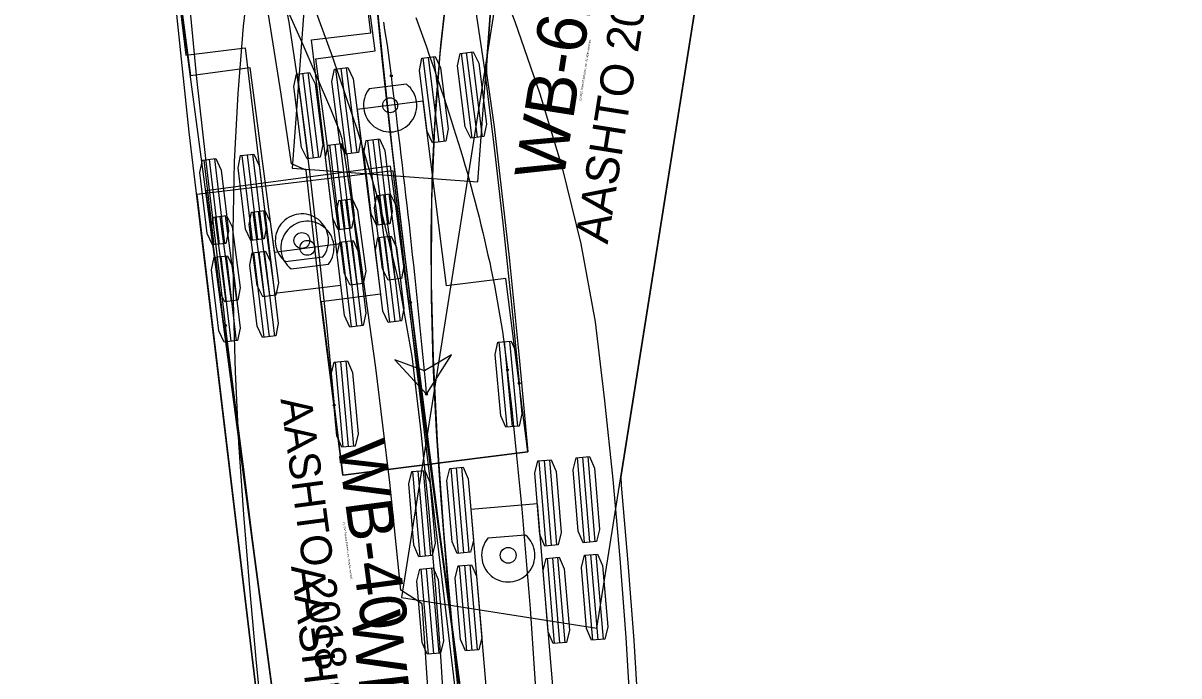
# Model space of a CAD drawing. Extents: x 1600240 to 1604759, y 285789 to 289704.
# Drawn here: x 1601615.79 to 1601665.41, y 286611.22 to 286639.24 of the extents above; entities that cross this region are included whole.
import ezdxf

# ---------------------------------------------------------------- set-up
doc = ezdxf.new("R2010")
doc.units = 0
for name, color, linetype in [('MT_P_CL_Double_Solid', 7, 'Continuous'), ('MT_X_Edge_Line', 7, 'Continuous'), ('TR_Turning_Path2', 7, 'Continuous'), ('TR_Turning_Path3', 7, 'Continuous'), ('TR_Turning_Path4', 7, 'Continuous')]:
    doc.layers.add(name, color=color, linetype=linetype)

msp = doc.modelspace()

# ---------------------------------------------------------------- linework, layer by layer
at = {"layer": 'MT_P_CL_Double_Solid'}
for p, q in [((1601630.904, 286638.054), (1601629.914, 286645.489)), ((1601621.984, 286644.432), (1601622.974, 286636.997)), ((1601628.36, 286637.715), (1601630.904, 286638.054)), ((1601622.974, 286636.997), (1601625.519, 286637.336)), ((1601625.519, 286637.336), (1601626.575, 286629.407)), ((1601629.417, 286629.785), (1601628.36, 286637.715)), ((1601631.565, 286633.098), (1601623.635, 286632.041)), ((1601635.924, 286600.387), (1601631.565, 286633.098)), ((1601623.635, 286632.041), (1601627.995, 286599.33)), ((1601623.635, 286632.041), (1601623.635, 286632.041)), ((1601631.038, 286631.851), (1601631.522, 286628.216)), ((1601631.265, 286631.881), (1601631.749, 286628.247)), ((1601631.492, 286631.911), (1601631.976, 286628.277)), ((1601629.402, 286631.633), (1601629.886, 286627.998)), ((1601629.629, 286631.663), (1601630.114, 286628.029)), ((1601629.856, 286631.693), (1601630.341, 286628.059)), ((1601624.016, 286630.915), (1601624.501, 286627.281)), ((1601624.243, 286630.945), (1601624.728, 286627.311)), ((1601624.471, 286630.976), (1601624.955, 286627.341)), ((1601625.652, 286631.133), (1601626.136, 286627.499)), ((1601625.879, 286631.163), (1601626.363, 286627.529)), ((1601626.106, 286631.194), (1601626.591, 286627.559)), ((1601626.575, 286629.407), (1601629.417, 286629.785)), ((1601627.302, 286628.688), (1601628.904, 286628.902))]:
    msp.add_line(p, q, dxfattribs=at)
for points in [[(1601624.486, 286626.267), (1601624.405, 286626.931), (1601624.004, 286630.248), (1601623.618, 286633.563), (1601623.255, 286636.871), (1601622.929, 286640.166), (1601622.653, 286643.44), (1601622.445, 286646.681), (1601622.323, 286649.878), (1601622.303, 286653.051), (1601622.401, 286656.2), (1601622.632, 286659.317), (1601623.004, 286662.393), (1601623.528, 286665.418), (1601624.209, 286668.384), (1601625.051, 286671.279), (1601626.056, 286674.095), (1601627.225, 286676.82), (1601628.556, 286679.444), (1601629.583, 286681.214)], [(1601632.426, 286627.244), (1601632.345, 286627.903), (1601631.948, 286631.194), (1601631.567, 286634.468), (1601631.211, 286637.711), (1601630.894, 286640.909), (1601630.63, 286644.047), (1601630.434, 286647.107), (1601630.321, 286650.076), (1601630.303, 286652.973), (1601630.392, 286655.803), (1601630.596, 286658.564), (1601630.923, 286661.252), (1601631.376, 286663.864), (1601631.958, 286666.395), (1601632.67, 286668.841), (1601633.512, 286671.196), (1601634.483, 286673.455), (1601635.579, 286675.612), (1601636.419, 286677.058)], [(1601633.596, 286671.411), (1601633.041, 286669.939), (1601632.543, 286668.446), (1601632.019, 286666.63), (1601631.64, 286665.099), (1601631.254, 286663.244), (1601630.894, 286661.06), (1601630.624, 286658.856), (1601630.44, 286656.637), (1601630.333, 286654.405), (1601630.297, 286652.164), (1601630.333, 286649.594), (1601630.438, 286647.019), (1601630.624, 286644.118), (1601630.866, 286641.217), (1601631.215, 286637.672), (1601631.642, 286633.807), (1601632.214, 286628.979), (1601633.671, 286617.403), (1601635.924, 286600.387), (1601627.995, 286599.33), (1601627.804, 286600.759)], [(1601627.804, 286600.759), (1601621.95, 286644.686), (1601621.785, 286646.064), (1601621.198, 286651.595), (1601620.682, 286656.836), (1601620.199, 286662.153), (1601619.748, 286667.57), (1601619.644, 286669.39), (1601619.607, 286670.84)], [(1601635.33, 286604.848), (1601634.89, 286608.147), (1601634.453, 286611.443), (1601634.019, 286614.736), (1601633.59, 286618.029), (1601633.168, 286621.32), (1601632.752, 286624.611), (1601632.426, 286627.244)], [(1601627.4, 286603.791), (1601626.96, 286607.092), (1601626.522, 286610.393), (1601626.087, 286613.696), (1601625.657, 286617.001), (1601625.232, 286620.309), (1601624.814, 286623.618), (1601624.486, 286626.267)]]:
    msp.add_lwpolyline(points, dxfattribs=at)
for points in [[(1601630.981, 286631.843), (1601631.548, 286631.919), (1601631.787, 286631.433), (1601632.136, 286628.816), (1601632.033, 286628.284), (1601631.466, 286628.209), (1601631.227, 286628.695), (1601630.878, 286631.312)], [(1601629.346, 286631.625), (1601629.913, 286631.701), (1601630.151, 286631.215), (1601630.5, 286628.598), (1601630.397, 286628.066), (1601629.83, 286627.991), (1601629.591, 286628.477), (1601629.243, 286631.094)], [(1601623.96, 286630.908), (1601624.527, 286630.983), (1601624.766, 286630.497), (1601625.114, 286627.88), (1601625.011, 286627.349), (1601624.444, 286627.273), (1601624.206, 286627.759), (1601623.857, 286630.376)], [(1601625.595, 286631.126), (1601626.162, 286631.201), (1601626.401, 286630.715), (1601626.75, 286628.098), (1601626.647, 286627.567), (1601626.08, 286627.491), (1601625.841, 286627.977), (1601625.492, 286630.594)]]:
    msp.add_lwpolyline(points, close=True, dxfattribs=at)
for centre, radius in [((1601627.996, 286629.596), 0.32), ((1601632.426, 286627.244), 0.0417), ((1601632.426, 286627.244), 0.0417), ((1601624.486, 286626.267), 0.0417), ((1601624.486, 286626.267), 0.0417)]:
    msp.add_circle(centre, radius, dxfattribs=at)
msp.add_arc((1601627.996, 286629.596), 1.143, 322.5914, 232.5914, dxfattribs=at)
at = {"layer": 'MT_X_Edge_Line'}
msp.add_arc((1602837.866, 287782.942), 1921, 229.7619, 229.7619, dxfattribs=at)
at = {"layer": 'TR_Turning_Path2'}
for p, q in [((1601629.768, 286665.929), (1601627.338, 286633.019)), ((1601635.316, 286632.43), (1601637.747, 286665.34)), ((1601633.882, 286634.163), (1601633.423, 286637.801)), ((1601635.064, 286634.312), (1601634.605, 286637.95)), ((1601635.292, 286634.341), (1601634.832, 286637.979)), ((1601635.519, 286634.369), (1601635.06, 286638.007)), ((1601629.901, 286633.66), (1601629.442, 286637.298)), ((1601630.128, 286633.689), (1601629.669, 286637.327)), ((1601633.427, 286634.105), (1601632.968, 286637.743)), ((1601633.655, 286634.134), (1601633.195, 286637.772)), ((1601628.037, 286633.425), (1601627.577, 286637.063)), ((1601628.264, 286633.454), (1601627.805, 286637.091)), ((1601628.491, 286633.482), (1601628.032, 286637.12)), ((1601629.674, 286633.632), (1601629.214, 286637.269)), ((1601632.249, 286636.619), (1601630.645, 286636.417)), ((1601632.97, 286635.896), (1601630.126, 286635.537)), ((1601633.972, 286627.959), (1601632.97, 286635.896)), ((1601630.126, 286635.537), (1601631.128, 286627.6)), ((1601627.338, 286633.019), (1601635.316, 286632.43)), ((1601635.316, 286632.43), (1601635.316, 286632.43)), ((1601636.519, 286628.28), (1601633.972, 286627.959)), ((1601637.458, 286620.839), (1601636.519, 286628.28)), ((1601631.128, 286627.6), (1601628.582, 286627.278)), ((1601628.582, 286627.278), (1601629.521, 286619.837)), ((1601636.57, 286621.896), (1601636.232, 286625.547)), ((1601636.798, 286621.917), (1601636.461, 286625.568)), ((1601637.026, 286621.938), (1601636.689, 286625.589)), ((1601629.538, 286621.04), (1601629.203, 286624.691)), ((1601629.766, 286621.061), (1601629.431, 286624.712)), ((1601629.994, 286621.082), (1601629.659, 286624.733)), ((1601629.521, 286619.837), (1601637.458, 286620.839)), ((1601637.458, 286620.839), (1601637.458, 286620.839))]:
    msp.add_line(p, q, dxfattribs=at)
for points in [[(1601621.785, 286664.025), (1601621.952, 286662.949), (1601622.604, 286659.411), (1601623.361, 286655.937), (1601624.18, 286652.522), (1601625.016, 286649.158), (1601625.826, 286645.835), (1601626.568, 286642.545), (1601627.202, 286639.282), (1601627.69, 286636.036), (1601628.097, 286632.743), (1601628.475, 286629.447), (1601628.824, 286626.147), (1601629.142, 286622.845)], [(1601629.677, 286663.347), (1601629.863, 286662.452), (1601630.549, 286659.447), (1601631.309, 286656.419), (1601632.111, 286653.36), (1601632.926, 286650.258), (1601633.718, 286647.104), (1601634.452, 286643.89), (1601635.091, 286640.609), (1601635.595, 286637.259), (1601636.013, 286633.896), (1601636.401, 286630.529), (1601636.759, 286627.159), (1601637.086, 286623.785)], [(1601637.473, 286661.627), (1601635.686, 286637.432), (1601635.678, 286637.097), (1601636.014, 286634.793), (1601636.658, 286629.187), (1601637.093, 286624.893), (1601637.458, 286620.839), (1601629.521, 286619.837), (1601628.579, 286627.299), (1601627.949, 286632.938), (1601627.311, 286633.207), (1601626.873, 286636.188), (1601626.022, 286641.522)], [(1601631.258, 286639.288), (1601631.312, 286638.959), (1601631.364, 286638.63), (1601631.414, 286638.3), (1601631.463, 286637.971), (1601631.51, 286637.641), (1601631.556, 286637.31), (1601631.599, 286636.98)], [(1601633.114, 286623.315), (1601634.181, 286625.006), (1601633.022, 286624.31), (1601631.756, 286624.783), (1601633.114, 286623.315)]]:
    msp.add_lwpolyline(points, dxfattribs=at)
for points in [[(1601633.938, 286634.17), (1601633.371, 286634.098), (1601633.136, 286634.586), (1601632.805, 286637.205), (1601632.912, 286637.736), (1601633.479, 286637.808), (1601633.714, 286637.32), (1601634.045, 286634.701)], [(1601635.575, 286634.377), (1601635.008, 286634.305), (1601634.773, 286634.793), (1601634.442, 286637.412), (1601634.549, 286637.943), (1601635.116, 286638.014), (1601635.351, 286637.527), (1601635.682, 286634.907)], [(1601630.185, 286633.696), (1601629.617, 286633.624), (1601629.382, 286634.112), (1601629.051, 286636.731), (1601629.158, 286637.262), (1601629.726, 286637.334), (1601629.961, 286636.846), (1601630.291, 286634.227)], [(1601628.548, 286633.489), (1601627.98, 286633.418), (1601627.745, 286633.905), (1601627.414, 286636.525), (1601627.521, 286637.056), (1601628.089, 286637.127), (1601628.324, 286636.64), (1601628.654, 286634.02)], [(1601637.083, 286621.944), (1601636.513, 286621.891), (1601636.294, 286622.386), (1601636.051, 286625.015), (1601636.176, 286625.542), (1601636.745, 286625.595), (1601636.964, 286625.099), (1601637.207, 286622.471)], [(1601633.114, 286623.315), (1601634.181, 286625.006), (1601633.022, 286624.31), (1601631.756, 286624.783)], [(1601630.051, 286621.087), (1601629.481, 286621.035), (1601629.263, 286621.53), (1601629.021, 286624.159), (1601629.146, 286624.686), (1601629.716, 286624.738), (1601629.934, 286624.243), (1601630.175, 286621.614)]]:
    msp.add_lwpolyline(points, close=True, dxfattribs=at)
for centre, radius in [((1601631.599, 286636.98), 0.0417), ((1601631.599, 286636.98), 0.0417), ((1601631.548, 286635.716), 0.32), ((1601637.086, 286623.785), 0.0417), ((1601633.114, 286623.315), 0.0417), ((1601629.142, 286622.845), 0.0417)]:
    msp.add_circle(centre, radius, dxfattribs=at)
for centre, radius, start, end in [((1601264.185, 286589.342), 370.49, 5.26113, 7.38754), ((1601631.548, 286635.716), 1.143, 142.195, 52.195)]:
    msp.add_arc(centre, radius, start, end, dxfattribs=at)
at = {"layer": 'TR_Turning_Path3'}
for p, q in [((1601630.72, 286638.826), (1601628.933, 286653.719)), ((1601620.99, 286652.766), (1601622.777, 286637.873)), ((1601628.171, 286638.52), (1601630.72, 286638.826)), ((1601629.434, 286627.996), (1601628.171, 286638.52)), ((1601622.777, 286637.873), (1601625.325, 286638.179)), ((1601625.325, 286638.179), (1601626.587, 286627.654)), ((1601628.943, 286634.013), (1601629.379, 286630.373)), ((1601629.17, 286634.041), (1601629.607, 286630.4)), ((1601629.398, 286634.068), (1601629.834, 286630.427)), ((1601630.581, 286634.21), (1601631.018, 286630.569)), ((1601630.808, 286634.237), (1601631.245, 286630.597)), ((1601631.036, 286634.264), (1601631.473, 286630.624)), ((1601623.548, 286633.366), (1601623.985, 286629.726)), ((1601623.776, 286633.394), (1601624.212, 286629.753)), ((1601624.003, 286633.421), (1601624.44, 286629.78)), ((1601625.186, 286633.563), (1601625.623, 286629.922)), ((1601625.414, 286633.59), (1601625.85, 286629.949)), ((1601625.641, 286633.617), (1601626.078, 286629.977)), ((1601631.682, 286632.898), (1601623.243, 286631.886)), ((1601637.399, 286585.24), (1601631.682, 286632.898)), ((1601623.243, 286631.886), (1601628.959, 286584.228)), ((1601623.243, 286631.886), (1601623.243, 286631.886)), ((1601629.443, 286629.843), (1601629.88, 286626.203)), ((1601629.67, 286629.871), (1601630.107, 286626.23)), ((1601629.898, 286629.898), (1601630.335, 286626.257)), ((1601631.081, 286630.04), (1601631.518, 286626.399)), ((1601631.309, 286630.067), (1601631.745, 286626.426)), ((1601631.536, 286630.094), (1601631.973, 286626.454)), ((1601625.686, 286629.393), (1601626.123, 286625.752)), ((1601625.914, 286629.42), (1601626.351, 286625.779)), ((1601626.142, 286629.447), (1601626.578, 286625.807)), ((1601624.048, 286629.196), (1601624.485, 286625.556)), ((1601624.276, 286629.223), (1601624.712, 286625.583)), ((1601624.503, 286629.251), (1601624.94, 286625.61)), ((1601627.054, 286629.011), (1601628.659, 286629.204)), ((1601626.587, 286627.654), (1601629.434, 286627.996))]:
    msp.add_line(p, q, dxfattribs=at)
for points in [[(1601628.788, 286585.657), (1601622.925, 286634.563), (1601622.405, 286639.474), (1601621.992, 286644.416), (1601620.944, 286653.156), (1601620.831, 286654.263), (1601620.727, 286655.731), (1601620.676, 286657.19), (1601620.707, 286661.917), (1601620.793, 286665.212), (1601620.912, 286668.155), (1601621, 286669.627), (1601621.142, 286671.084)], [(1601626.64, 286603.897), (1601626.494, 286605.221), (1601626.143, 286608.515), (1601625.815, 286611.777), (1601625.519, 286614.992), (1601625.264, 286618.142), (1601625.059, 286621.219), (1601624.908, 286624.272), (1601624.821, 286627.304), (1601624.807, 286630.308), (1601624.871, 286633.282), (1601625.02, 286636.221), (1601625.259, 286639.119), (1601625.591, 286641.974), (1601626.019, 286644.782), (1601626.545, 286647.537), (1601627.171, 286650.235), (1601627.668, 286652.089)], [(1601635.088, 286604.837), (1601634.944, 286606.147), (1601634.597, 286609.397), (1601634.275, 286612.598), (1601633.987, 286615.732), (1601633.74, 286618.778), (1601633.544, 286621.724), (1601633.401, 286624.616), (1601633.32, 286627.459), (1601633.307, 286630.252), (1601633.366, 286632.99), (1601633.503, 286635.672), (1601633.719, 286638.296), (1601634.017, 286640.86), (1601634.399, 286643.36), (1601634.865, 286645.796), (1601635.415, 286648.164), (1601635.849, 286649.781)], [(1601634.002, 286640.755), (1601633.683, 286637.93), (1601633.447, 286634.768), (1601633.325, 286631.586), (1601633.31, 286628.067), (1601633.391, 286624.857), (1601633.567, 286621.317), (1601633.843, 286617.451), (1601634.242, 286612.937), (1601634.733, 286608.1)]]:
    msp.add_lwpolyline(points, dxfattribs=at)
for points in [[(1601628.886, 286634.007), (1601629.454, 286634.075), (1601629.686, 286633.586), (1601630.001, 286630.964), (1601629.891, 286630.434), (1601629.323, 286630.366), (1601629.091, 286630.855), (1601628.776, 286633.476)], [(1601630.524, 286634.203), (1601631.092, 286634.271), (1601631.325, 286633.782), (1601631.639, 286631.161), (1601631.529, 286630.631), (1601630.961, 286630.563), (1601630.729, 286631.052), (1601630.414, 286633.673)], [(1601623.492, 286633.359), (1601624.059, 286633.428), (1601624.292, 286632.938), (1601624.606, 286630.317), (1601624.496, 286629.787), (1601623.928, 286629.719), (1601623.696, 286630.208), (1601623.382, 286632.829)], [(1601625.13, 286633.556), (1601625.698, 286633.624), (1601625.93, 286633.135), (1601626.244, 286630.514), (1601626.134, 286629.984), (1601625.566, 286629.915), (1601625.334, 286630.405), (1601625.02, 286633.026)], [(1601629.386, 286629.836), (1601629.954, 286629.905), (1601630.187, 286629.415), (1601630.501, 286626.794), (1601630.391, 286626.264), (1601629.823, 286626.196), (1601629.591, 286626.685), (1601629.276, 286629.306)], [(1601631.025, 286630.033), (1601631.593, 286630.101), (1601631.825, 286629.612), (1601632.139, 286626.991), (1601632.029, 286626.461), (1601631.461, 286626.392), (1601631.229, 286626.882), (1601630.915, 286629.503)], [(1601625.63, 286629.386), (1601626.198, 286629.454), (1601626.43, 286628.965), (1601626.745, 286626.344), (1601626.635, 286625.813), (1601626.067, 286625.745), (1601625.834, 286626.234), (1601625.52, 286628.856)], [(1601623.992, 286629.189), (1601624.56, 286629.258), (1601624.792, 286628.768), (1601625.106, 286626.147), (1601624.996, 286625.617), (1601624.428, 286625.549), (1601624.196, 286626.038), (1601623.882, 286628.659)]]:
    msp.add_lwpolyline(points, close=True, dxfattribs=at)
msp.add_circle((1601627.76, 286629.91), 0.34, dxfattribs=at)
msp.add_arc((1601627.76, 286629.91), 1.143, 321.8399, 231.8399, dxfattribs=at)
at = {"layer": 'TR_Turning_Path4'}
for p, q in [((1601639.524, 286661.999), (1601632.03, 286614.588)), ((1601640.426, 286613.261), (1601647.919, 286660.672)), ((1601638.253, 286616.799), (1601637.943, 286620.453)), ((1601638.481, 286616.819), (1601638.172, 286620.472)), ((1601638.709, 286616.838), (1601638.4, 286620.492)), ((1601639.897, 286616.938), (1601639.588, 286620.592)), ((1601640.125, 286616.958), (1601639.816, 286620.611)), ((1601640.353, 286616.977), (1601640.044, 286620.631)), ((1601632.839, 286616.341), (1601632.529, 286619.995)), ((1601633.067, 286616.36), (1601632.758, 286620.014)), ((1601633.295, 286616.38), (1601632.986, 286620.033)), ((1601634.483, 286616.48), (1601634.174, 286620.134)), ((1601634.711, 286616.5), (1601634.402, 286620.153)), ((1601634.939, 286616.519), (1601634.63, 286620.173)), ((1601637.87, 286618.607), (1601635.013, 286618.365)), ((1601638.763, 286608.044), (1601637.87, 286618.607)), ((1601635.013, 286618.365), (1601635.907, 286607.803)), ((1601637.356, 286617.267), (1601635.745, 286617.13)), ((1601640.707, 286612.792), (1601640.398, 286616.446)), ((1601634.837, 286612.295), (1601634.528, 286615.949)), ((1601635.065, 286612.315), (1601634.756, 286615.968)), ((1601635.293, 286612.334), (1601634.984, 286615.987)), ((1601638.607, 286612.614), (1601638.297, 286616.268)), ((1601638.835, 286612.634), (1601638.526, 286616.287)), ((1601639.063, 286612.653), (1601638.754, 286616.306)), ((1601640.251, 286612.753), (1601639.942, 286616.407)), ((1601640.479, 286612.773), (1601640.17, 286616.426)), ((1601633.193, 286612.156), (1601632.884, 286615.81)), ((1601633.421, 286612.175), (1601633.112, 286615.829)), ((1601633.649, 286612.195), (1601633.34, 286615.848)), ((1601632.03, 286614.588), (1601640.426, 286613.261)), ((1601640.426, 286613.261), (1601640.426, 286613.261))]:
    msp.add_line(p, q, dxfattribs=at)
for points in [[(1601650.815, 286672.273), (1601649.936, 286669.265), (1601649.283, 286666.736), (1601648.694, 286664.185), (1601648.162, 286661.611), (1601647.588, 286658.487), (1601641.451, 286619.743), (1601641.459, 286619.408), (1601641.753, 286616.075), (1601642.003, 286612.737), (1601642.209, 286609.396)], [(1601633.274, 286609.024), (1601632.925, 286614.317), (1601632.001, 286614.903), (1601631.529, 286619.515), (1601630.934, 286624.445), (1601630.251, 286629.364), (1601629.486, 286634.272), (1601629.385, 286634.594), (1601628.995, 286635.549), (1601627.777, 286638.407), (1601623.954, 286646.917), (1601622.636, 286649.946), (1601621.746, 286652.27), (1601621.22, 286653.841), (1601620.863, 286655.029), (1601620.437, 286656.624), (1601619.982, 286658.634), (1601619.616, 286660.656), (1601619.338, 286662.689), (1601619.149, 286664.727), (1601619.047, 286666.768), (1601619.034, 286668.807), (1601619.108, 286670.841)], [(1601623.417, 286652.845), (1601624.145, 286650.831), (1601625.393, 286647.518), (1601626.656, 286644.247), (1601627.896, 286641.005), (1601629.077, 286637.784), (1601630.163, 286634.572), (1601631.117, 286631.362), (1601631.903, 286628.152), (1601632.485, 286624.944), (1601632.872, 286621.697), (1601633.201, 286618.417), (1601633.487, 286615.134), (1601633.729, 286611.847), (1601633.927, 286608.557), (1601634.08, 286605.264), (1601634.19, 286601.971), (1601634.255, 286598.675), (1601634.274, 286596.698)], [(1601631.252, 286652.811), (1601631.998, 286651.098), (1601633.256, 286648.219), (1601634.51, 286645.304), (1601635.734, 286642.34), (1601636.901, 286639.314), (1601637.979, 286636.214), (1601638.936, 286633.033), (1601639.738, 286629.768), (1601640.346, 286626.419), (1601640.756, 286623.029), (1601641.102, 286619.645), (1601641.404, 286616.257), (1601641.66, 286612.865), (1601641.87, 286609.469), (1601642.035, 286606.072), (1601642.155, 286602.672), (1601642.229, 286599.27), (1601642.252, 286597.229)], [(1601632.647, 286639.482), (1601632.762, 286639.17), (1601632.877, 286638.857), (1601632.991, 286638.543), (1601633.103, 286638.23), (1601633.215, 286637.916), (1601633.326, 286637.601), (1601633.436, 286637.287), (1601633.545, 286636.971), (1601633.652, 286636.656), (1601633.759, 286636.34), (1601633.864, 286636.024), (1601633.969, 286635.707), (1601634.072, 286635.39), (1601634.173, 286635.073), (1601634.274, 286634.755), (1601634.373, 286634.437), (1601634.471, 286634.118), (1601634.567, 286633.799), (1601634.662, 286633.48), (1601634.756, 286633.16), (1601634.848, 286632.839), (1601634.938, 286632.518), (1601635.027, 286632.197), (1601635.114, 286631.875), (1601635.2, 286631.553), (1601635.284, 286631.231), (1601635.366, 286630.908), (1601635.446, 286630.584), (1601635.525, 286630.26), (1601635.602, 286629.936), (1601635.676, 286629.611), (1601635.749, 286629.286), (1601635.821, 286628.96), (1601635.89, 286628.634), (1601635.957, 286628.307), (1601636.022, 286627.98), (1601636.084, 286627.653), (1601636.145, 286627.325), (1601636.204, 286626.997), (1601636.26, 286626.669), (1601636.314, 286626.34), (1601636.366, 286626.01), (1601636.416, 286625.681), (1601636.463, 286625.351), (1601636.507, 286625.021), (1601636.55, 286624.69), (1601636.59, 286624.359)]]:
    msp.add_lwpolyline(points, dxfattribs=at)
for points in [[(1601638.766, 286616.843), (1601638.196, 286616.794), (1601637.981, 286617.291), (1601637.758, 286619.922), (1601637.887, 286620.448), (1601638.457, 286620.496), (1601638.672, 286619.999), (1601638.894, 286617.369)], [(1601640.41, 286616.982), (1601639.84, 286616.934), (1601639.625, 286617.431), (1601639.402, 286620.061), (1601639.531, 286620.587), (1601640.101, 286620.635), (1601640.316, 286620.138), (1601640.538, 286617.508)], [(1601633.352, 286616.385), (1601632.782, 286616.336), (1601632.567, 286616.833), (1601632.344, 286619.464), (1601632.473, 286619.99), (1601633.043, 286620.038), (1601633.258, 286619.541), (1601633.48, 286616.911)], [(1601634.996, 286616.524), (1601634.426, 286616.475), (1601634.211, 286616.972), (1601633.988, 286619.603), (1601634.117, 286620.129), (1601634.687, 286620.177), (1601634.902, 286619.68), (1601635.124, 286617.05)], [(1601640.764, 286612.797), (1601640.194, 286612.749), (1601639.979, 286613.246), (1601639.757, 286615.876), (1601639.885, 286616.402), (1601640.455, 286616.45), (1601640.67, 286615.953), (1601640.893, 286613.323)], [(1601635.35, 286612.339), (1601634.78, 286612.29), (1601634.565, 286612.787), (1601634.343, 286615.418), (1601634.471, 286615.944), (1601635.041, 286615.992), (1601635.256, 286615.495), (1601635.479, 286612.865)], [(1601639.12, 286612.658), (1601638.55, 286612.609), (1601638.335, 286613.106), (1601638.112, 286615.737), (1601638.241, 286616.263), (1601638.811, 286616.311), (1601639.026, 286615.814), (1601639.248, 286613.184)], [(1601633.706, 286612.2), (1601633.136, 286612.151), (1601632.921, 286612.648), (1601632.698, 286615.279), (1601632.827, 286615.805), (1601633.397, 286615.853), (1601633.612, 286615.356), (1601633.834, 286612.726)]]:
    msp.add_lwpolyline(points, close=True, dxfattribs=at)
for centre, radius in [((1601636.59, 286624.359), 0.0417), ((1601636.59, 286624.359), 0.0417), ((1601636.618, 286616.393), 0.34)]:
    msp.add_circle(centre, radius, dxfattribs=at)
for centre, radius, start, end in [((1601388.002, 286595.43), 250.265, 0.35089, 6.63781), ((1601636.618, 286616.393), 1.143, 139.8365, 49.8365)]:
    msp.add_arc(centre, radius, start, end, dxfattribs=at)

# ---------------------------------------------------------------- texts
at = {"layer": 'MT_P_CL_Double_Solid'}
for s, height, p in [('AASHTO 2018 (US)', 1.33333, (1601626.838, 286623.1)), ('WB-40', 2, (1601629.278, 286621.192)), ('(c) 2024 Transoft Solutions, Inc. All rights reserved.', 0.08, (1601629.524, 286617.833))]:
    msp.add_text(s, height=height, rotation=277.5914, dxfattribs=at).set_placement(p)
at = {"layer": 'TR_Turning_Path3'}
for s, height, p in [('AASHTO 2018 (US)', 1.41667, (1601627.291, 286615.92)), ('WB-62', 2.125, (1601629.857, 286613.858))]:
    msp.add_text(s, height=height, rotation=276.8399, dxfattribs=at).set_placement(p)
at = {"layer": 'TR_Turning_Path4'}
for s, height, p in [('AASHTO 2018 (US)', 1.41667, (1601640.884, 286629.726)), ('WB-62', 2.125, (1601638.978, 286632.409)), ('(c) 2024 Transoft Solutions, Inc. All rights reserved.', 0.085, (1601639.745, 286635.904))]:
    msp.add_text(s, height=height, rotation=81.0186, dxfattribs=at).set_placement(p)

doc.saveas('drawing.dxf')
